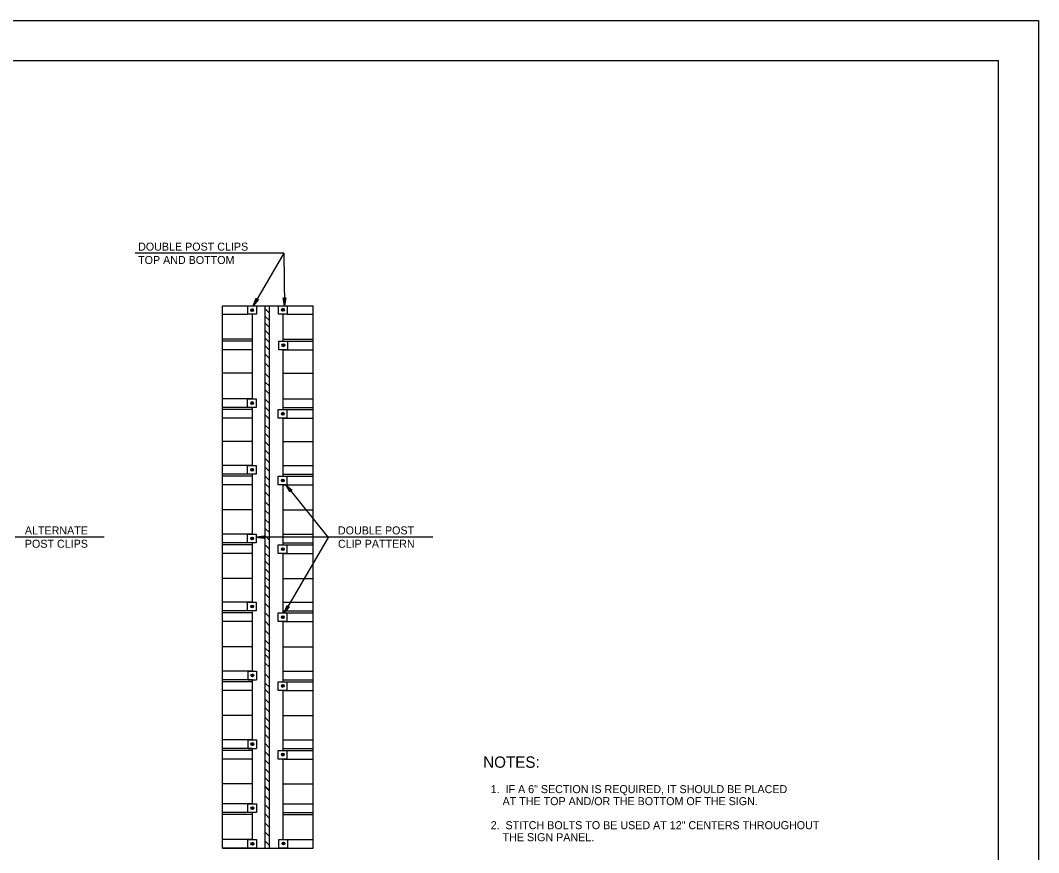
# Model space of a CAD drawing. Extents: x 647822 to 649292, y 298458 to 299646.
# Drawn here: x 648281.8 to 648663.3, y 299333.8 to 299645.6 of the extents above; entities that cross this region are included whole.
import ezdxf

# ---------------------------------------------------------------- set-up
doc = ezdxf.new("R2010")
doc.units = 0
for name, color, linetype in [('1', 7, 'Continuous'), ('2', 7, 'Continuous'), ('3', 7, 'Continuous'), ('XCS-GRID-MIN', 7, 'Continuous')]:
    doc.layers.add(name, color=color, linetype=linetype)

# ---------------------------------------------------------------- blocks, each defined once
blk = doc.blocks.new('RARROW')
at = {"layer": '3'}
blk.add_lwpolyline([(-2.2695, 0.285), (-2.184875, 0.12075), (0, 0), (-2.2695, 0.285), (-2.38575, 0.384625), (0, 0), (-2.183125, -0.108), (-2.262875, -0.2705), (0, 0), (-2.38575, -0.379125), (-2.262875, -0.2705)], dxfattribs=at)

msp = doc.modelspace()

# ---------------------------------------------------------------- linework, layer by layer
at = {"layer": '1'}
for p in [(647862.31, 299630.63), (648648.31, 299066.63)]:
    msp.add_line(p, (648648.31, 299630.63), dxfattribs=at)
at = {"layer": '2'}
for p, q in [((648380.55, 299558.35), (648324.89, 299558.35)), ((648380.55, 299558.35), (648369.05, 299538.73)), ((648380.55, 299558.35), (648380.8, 299538.73)), ((648357.55, 299335.47), (648357.55, 299538.73)), ((648357.55, 299538.73), (648391.55, 299538.73)), ((648367.05, 299535.6), (648367.05, 299538.73)), ((648370.3, 299538.73), (648370.3, 299535.6)), ((648373.55, 299335.47), (648373.55, 299538.73)), ((648375.18, 299535.98), (648373.55, 299537.6)), ((648375.18, 299335.47), (648375.18, 299538.73)), ((648378.55, 299538.73), (648381.8, 299538.73)), ((648378.55, 299535.6), (648378.55, 299538.73)), ((648381.8, 299538.73), (648381.8, 299535.6)), ((648391.55, 299335.47), (648391.55, 299538.73)), ((648357.55, 299535.6), (648367.05, 299535.6)), ((648370.3, 299535.6), (648367.05, 299535.6)), ((648368.8, 299503.85), (648368.8, 299535.6)), ((648375.18, 299533.23), (648373.55, 299534.73)), ((648381.8, 299535.6), (648378.55, 299535.6)), ((648380.3, 299525.48), (648380.3, 299535.6)), ((648381.8, 299535.6), (648391.55, 299535.6)), ((648375.18, 299530.6), (648373.55, 299532.23)), ((648368.8, 299526.23), (648357.55, 299526.23)), ((648375.18, 299527.85), (648373.55, 299529.48)), ((648375.18, 299524.98), (648373.55, 299526.6)), ((648380.3, 299526.23), (648391.55, 299526.23)), ((648368.8, 299525.48), (648357.55, 299525.48)), ((648368.8, 299522.23), (648357.55, 299522.23)), ((648375.18, 299522.1), (648373.55, 299523.73)), ((648378.68, 299525.48), (648381.93, 299525.48)), ((648378.68, 299522.23), (648378.68, 299525.48)), ((648381.93, 299522.23), (648378.68, 299522.23)), ((648380.3, 299525.48), (648391.55, 299525.48)), ((648380.3, 299525.48), (648380.3, 299525.48)), ((648380.3, 299522.23), (648391.55, 299522.23)), ((648380.3, 299499.85), (648380.3, 299522.23)), ((648381.93, 299525.48), (648381.93, 299522.23)), ((648375.18, 299518.98), (648373.55, 299520.6)), ((648375.18, 299515.6), (648373.55, 299517.23)), ((648368.8, 299513.48), (648357.55, 299513.48)), ((648375.18, 299511.73), (648373.55, 299513.35)), ((648380.3, 299513.48), (648391.55, 299513.48)), ((648375.18, 299508.6), (648373.55, 299510.1)), ((648375.18, 299505.6), (648373.55, 299507.23)), ((648368.8, 299503.85), (648357.55, 299503.85)), ((648366.93, 299503.85), (648370.18, 299503.85)), ((648366.93, 299500.6), (648366.93, 299503.85)), ((648370.18, 299503.85), (648370.18, 299500.6)), ((648375.18, 299502.1), (648373.55, 299503.73)), ((648380.3, 299503.85), (648391.55, 299503.85)), ((648368.8, 299500.6), (648357.55, 299500.6)), ((648368.8, 299499.85), (648357.55, 299499.85)), ((648370.18, 299500.6), (648366.93, 299500.6)), ((648368.8, 299478.85), (648368.8, 299500.6)), ((648375.18, 299499.1), (648373.55, 299500.73)), ((648378.43, 299499.85), (648381.68, 299499.85)), ((648378.43, 299496.6), (648378.43, 299499.85)), ((648380.3, 299500.6), (648391.55, 299500.6)), ((648380.3, 299499.85), (648391.55, 299499.85)), ((648381.68, 299499.85), (648381.68, 299496.6)), ((648368.8, 299496.6), (648357.55, 299496.6)), ((648375.18, 299496.23), (648373.55, 299497.85)), ((648381.68, 299496.6), (648378.43, 299496.6)), ((648380.3, 299496.6), (648391.55, 299496.6)), ((648380.3, 299474.85), (648380.3, 299496.6)), ((648375.18, 299492.48), (648373.55, 299493.98)), ((648368.8, 299487.85), (648357.55, 299487.85)), ((648375.18, 299489.23), (648373.55, 299490.85)), ((648380.3, 299487.85), (648391.55, 299487.85)), ((648375.18, 299486.1), (648373.55, 299487.73)), ((648375.18, 299482.98), (648373.55, 299484.6)), ((648375.18, 299479.85), (648373.55, 299481.48)), ((648368.8, 299478.85), (648357.55, 299478.85)), ((648366.93, 299478.85), (648370.18, 299478.85)), ((648366.93, 299475.6), (648366.93, 299478.85)), ((648370.18, 299478.85), (648370.18, 299475.6)), ((648375.18, 299476.6), (648373.55, 299478.23)), ((648380.3, 299478.85), (648391.55, 299478.85)), ((648368.8, 299475.6), (648357.55, 299475.6)), ((648368.8, 299474.85), (648357.55, 299474.85)), ((648370.18, 299475.6), (648366.93, 299475.6)), ((648368.8, 299453.47), (648368.8, 299475.6)), ((648375.18, 299473.23), (648373.55, 299474.85)), ((648378.43, 299474.85), (648381.68, 299474.85)), ((648378.43, 299471.6), (648378.43, 299474.85)), ((648380.3, 299475.6), (648391.55, 299475.6)), ((648380.3, 299474.85), (648391.55, 299474.85)), ((648381.68, 299474.85), (648381.68, 299471.6)), ((648368.8, 299471.6), (648357.55, 299471.6)), ((648375.18, 299470.48), (648373.55, 299471.98)), ((648375.18, 299467.23), (648373.55, 299468.85)), ((648381.68, 299471.6), (648378.43, 299471.6)), ((648380.3, 299471.6), (648391.55, 299471.6)), ((648380.3, 299449.36), (648380.3, 299471.6)), ((648381.32, 299471.6), (648397.18, 299451.85)), ((648375.18, 299463.6), (648373.55, 299465.23)), ((648368.8, 299462.23), (648357.55, 299462.23)), ((648375.18, 299460.48), (648373.55, 299461.98)), ((648380.3, 299462.23), (648391.55, 299462.23)), ((648375.18, 299457.1), (648373.55, 299458.6)), ((648375.18, 299453.73), (648373.55, 299455.23)), ((648313.17, 299451.98), (648279.88, 299451.98)), ((648368.8, 299453.1), (648357.55, 299453.1)), ((648368.8, 299449.85), (648357.55, 299449.85)), ((648366.93, 299453.1), (648370.18, 299453.1)), ((648366.93, 299449.85), (648366.93, 299453.1)), ((648370.18, 299449.85), (648366.93, 299449.85)), ((648368.55, 299453.1), (648368.55, 299453.1)), ((648368.8, 299427.6), (648368.8, 299449.85)), ((648370.18, 299453.1), (648370.18, 299449.85)), ((648397.43, 299451.98), (648370.3, 299451.98)), ((648375.18, 299450.85), (648373.55, 299452.48)), ((648380.3, 299453.1), (648391.55, 299453.1)), ((648380.3, 299449.85), (648391.55, 299449.85)), ((648397.18, 299451.85), (648380.71, 299423.6)), ((648436.31, 299451.98), (648397.18, 299451.98)), ((648368.8, 299449.1), (648357.55, 299449.1)), ((648368.8, 299445.85), (648357.55, 299445.85)), ((648375.18, 299447.48), (648373.55, 299449.1)), ((648375.18, 299444.48), (648373.55, 299445.98)), ((648378.43, 299449.1), (648381.68, 299449.1)), ((648378.43, 299445.85), (648378.43, 299449.1)), ((648381.68, 299445.85), (648378.43, 299445.85)), ((648380.05, 299449.1), (648380.05, 299449.1)), ((648380.3, 299449.1), (648391.55, 299449.1)), ((648380.3, 299445.85), (648391.55, 299445.85)), ((648380.3, 299423.6), (648380.3, 299445.85)), ((648381.68, 299449.1), (648381.68, 299445.85)), ((648375.18, 299441.35), (648373.55, 299442.98)), ((648375.18, 299438.48), (648373.55, 299440.1)), ((648368.8, 299436.48), (648357.55, 299436.48)), ((648375.18, 299435.48), (648373.55, 299436.98)), ((648380.3, 299436.48), (648391.55, 299436.48)), ((648375.05, 299432.48), (648373.55, 299433.98)), ((648375.18, 299432.48), (648373.55, 299433.98)), ((648375.18, 299429.1), (648373.55, 299430.73)), ((648368.68, 299427.6), (648357.43, 299427.6)), ((648366.93, 299427.6), (648370.18, 299427.6)), ((648366.93, 299424.35), (648366.93, 299427.6)), ((648368.55, 299427.6), (648368.55, 299427.6)), ((648370.18, 299427.6), (648370.18, 299424.35)), ((648375.18, 299425.48), (648373.55, 299427.1)), ((648380.3, 299427.6), (648391.55, 299427.6)), ((648368.68, 299424.35), (648357.43, 299424.35)), ((648368.68, 299423.6), (648357.43, 299423.6)), ((648370.18, 299424.35), (648366.93, 299424.35)), ((648368.8, 299401.85), (648368.8, 299424.02)), ((648375.18, 299421.98), (648373.55, 299423.6)), ((648378.43, 299423.6), (648381.68, 299423.6)), ((648378.43, 299420.35), (648378.43, 299423.6)), ((648380.05, 299423.6), (648380.05, 299423.6)), ((648380.3, 299424.35), (648391.55, 299424.35)), ((648380.3, 299423.6), (648391.55, 299423.6)), ((648381.68, 299423.6), (648381.68, 299420.35)), ((648368.68, 299420.35), (648357.43, 299420.35)), ((648375.18, 299418.73), (648373.68, 299420.35)), ((648381.68, 299420.35), (648378.43, 299420.35)), ((648380.3, 299420.35), (648391.55, 299420.35)), ((648380.3, 299397.85), (648380.3, 299420.27)), ((648375.18, 299415.35), (648373.55, 299416.98)), ((648375.18, 299411.73), (648373.55, 299413.35)), ((648368.8, 299410.85), (648357.55, 299410.85)), ((648375.18, 299408.85), (648373.55, 299410.35)), ((648375.18, 299406.35), (648373.55, 299407.98)), ((648380.3, 299410.85), (648391.55, 299410.85)), ((648375.18, 299403.23), (648373.55, 299404.85)), ((648368.8, 299401.85), (648357.55, 299401.85)), ((648367.18, 299401.85), (648370.3, 299401.85)), ((648367.18, 299398.6), (648367.18, 299401.85)), ((648368.8, 299401.85), (648368.8, 299401.85)), ((648370.3, 299401.85), (648370.3, 299398.6)), ((648375.18, 299399.1), (648373.55, 299400.73)), ((648380.3, 299401.85), (648391.55, 299401.85)), ((648368.8, 299398.6), (648357.55, 299398.6)), ((648368.8, 299397.85), (648357.55, 299397.85)), ((648368.8, 299398.6), (648367.18, 299398.6)), ((648367.18, 299398.6), (648370.3, 299398.6)), ((648368.8, 299376.1), (648368.8, 299398.6)), ((648375.18, 299395.85), (648373.55, 299397.35)), ((648378.43, 299397.85), (648381.68, 299397.85)), ((648378.43, 299394.6), (648378.43, 299397.85)), ((648380.05, 299397.85), (648380.05, 299397.85)), ((648380.3, 299398.6), (648391.55, 299398.6)), ((648380.3, 299397.85), (648391.55, 299397.85)), ((648381.68, 299397.85), (648381.68, 299394.6)), ((648368.8, 299394.6), (648357.55, 299394.6)), ((648375.18, 299393.35), (648373.55, 299394.98)), ((648381.68, 299394.6), (648378.43, 299394.6)), ((648380.3, 299394.6), (648391.55, 299394.6)), ((648380.3, 299372.1), (648380.3, 299394.6)), ((648375.18, 299389.73), (648373.55, 299391.35)), ((648368.8, 299385.23), (648357.55, 299385.23)), ((648375.18, 299386.48), (648373.55, 299388.1)), ((648380.3, 299385.23), (648391.55, 299385.23)), ((648375.18, 299382.85), (648373.55, 299384.48)), ((648375.18, 299379.85), (648373.55, 299381.48)), ((648375.18, 299376.48), (648373.55, 299378.1)), ((648368.8, 299376.1), (648357.55, 299376.1)), ((648367.18, 299376.1), (648370.3, 299376.1)), ((648367.18, 299372.85), (648367.18, 299376.1)), ((648368.8, 299376.1), (648368.8, 299376.1)), ((648370.3, 299376.1), (648370.3, 299372.85)), ((648375.05, 299373.1), (648373.55, 299374.73)), ((648380.3, 299376.1), (648391.55, 299376.1)), ((648368.8, 299372.85), (648357.55, 299372.85)), ((648368.8, 299372.1), (648357.55, 299372.1)), ((648368.8, 299372.85), (648367.18, 299372.85)), ((648367.18, 299372.85), (648370.3, 299372.85)), ((648368.8, 299352.1), (648368.8, 299372.85)), ((648375.05, 299370.1), (648373.55, 299371.6)), ((648378.43, 299372.1), (648381.68, 299372.1)), ((648378.43, 299368.85), (648378.43, 299372.1)), ((648380.3, 299372.85), (648391.55, 299372.85)), ((648380.3, 299372.1), (648391.55, 299372.1)), ((648381.68, 299372.1), (648381.68, 299368.85)), ((648368.8, 299368.85), (648357.55, 299368.85)), ((648375.18, 299366.85), (648373.55, 299368.48)), ((648381.68, 299368.85), (648378.43, 299368.85)), ((648380.3, 299368.85), (648391.55, 299368.85)), ((648380.3, 299348.05), (648380.3, 299368.85)), ((648375.18, 299363.6), (648373.68, 299365.1)), ((648368.8, 299359.6), (648357.55, 299359.6)), ((648375.18, 299360.23), (648373.55, 299361.85)), ((648375.18, 299360.23), (648373.55, 299361.85)), ((648375.05, 299357.23), (648373.55, 299358.73)), ((648375.18, 299356.83), (648373.55, 299358.46)), ((648380.3, 299359.6), (648391.55, 299359.6)), ((648375.18, 299353.44), (648373.55, 299355.06)), ((648368.68, 299352.1), (648357.55, 299352.1)), ((648367.05, 299352.1), (648370.3, 299352.1)), ((648367.05, 299348.85), (648367.05, 299352.1)), ((648370.3, 299352.1), (648370.3, 299348.85)), ((648375.18, 299350.04), (648373.55, 299351.67)), ((648380.43, 299352.1), (648391.55, 299352.1)), ((648368.68, 299348.85), (648357.55, 299348.85)), ((648368.8, 299348.05), (648357.55, 299348.05)), ((648370.3, 299348.85), (648367.05, 299348.85)), ((648368.8, 299338.72), (648368.8, 299348.85)), ((648375.18, 299346.65), (648373.55, 299348.28)), ((648380.3, 299348.85), (648391.55, 299348.85)), ((648380.3, 299338.72), (648380.3, 299348.05)), ((648380.3, 299348.05), (648391.55, 299348.05)), ((648375.18, 299343.26), (648373.55, 299344.88)), ((648375.18, 299339.86), (648373.55, 299341.49)), ((648368.68, 299338.72), (648357.55, 299338.72)), ((648357.55, 299335.47), (648391.55, 299335.47)), ((648368.68, 299335.47), (648357.55, 299335.47)), ((648367.05, 299338.72), (648370.3, 299338.72)), ((648367.05, 299335.47), (648367.05, 299338.72)), ((648370.3, 299335.47), (648367.05, 299335.47)), ((648370.3, 299338.72), (648370.3, 299335.47)), ((648375.18, 299336.47), (648373.55, 299338.09)), ((648378.68, 299338.72), (648381.93, 299338.72)), ((648378.68, 299335.47), (648378.68, 299338.72)), ((648381.93, 299335.47), (648378.68, 299335.47)), ((648380.43, 299338.72), (648391.55, 299338.72)), ((648380.43, 299335.47), (648391.55, 299335.47)), ((648381.93, 299338.72), (648381.93, 299335.47))]:
    msp.add_line(p, q, dxfattribs=at)
for points in [[(648368.55, 299537.48), (648368.43, 299537.23), (648368.43, 299536.85), (648368.68, 299536.73), (648368.93, 299536.85), (648369.05, 299537.1), (648369.05, 299537.35), (648368.93, 299537.48), (648368.68, 299537.48), (648368.55, 299537.23), (648368.55, 299537.1), (648368.55, 299536.98), (648368.68, 299536.98), (648368.8, 299537.1), (648368.93, 299537.23), (648368.8, 299537.35), (648368.8, 299537.23), (648368.68, 299537.1)], [(648380.05, 299537.6), (648379.93, 299537.23), (648379.93, 299536.98), (648380.18, 299536.85), (648380.43, 299536.98), (648380.55, 299537.23), (648380.55, 299537.48), (648380.43, 299537.6), (648380.18, 299537.48), (648380.05, 299537.23), (648380.05, 299537.1), (648380.05, 299537.1), (648380.18, 299536.98), (648380.3, 299537.23), (648380.43, 299537.23), (648380.3, 299537.48), (648380.3, 299537.35), (648380.18, 299537.1)], [(648380.18, 299524.35), (648380.05, 299523.98), (648380.05, 299523.73), (648380.3, 299523.48), (648380.55, 299523.6), (648380.68, 299523.85), (648380.68, 299524.1), (648380.55, 299524.35), (648380.43, 299524.23), (648380.18, 299523.98), (648380.18, 299523.85), (648380.18, 299523.73), (648380.3, 299523.73), (648380.43, 299523.85), (648380.55, 299523.98), (648380.55, 299524.1), (648380.43, 299523.98), (648380.3, 299523.85)], [(648368.55, 299502.6), (648368.3, 299502.35), (648368.3, 299501.98), (648368.55, 299501.85), (648368.8, 299501.98), (648368.93, 299502.23), (648368.93, 299502.48), (648368.8, 299502.6), (648368.68, 299502.6), (648368.43, 299502.35), (648368.43, 299502.23), (648368.43, 299502.1), (648368.68, 299502.1), (648368.8, 299502.23), (648368.8, 299502.35), (648368.8, 299502.48), (648368.68, 299502.35), (648368.55, 299502.23)], [(648380.05, 299498.6), (648379.8, 299498.35), (648379.8, 299497.98), (648380.05, 299497.85), (648380.3, 299497.98), (648380.43, 299498.23), (648380.43, 299498.48), (648380.3, 299498.6), (648380.18, 299498.6), (648379.93, 299498.35), (648379.93, 299498.23), (648379.93, 299498.1), (648380.18, 299498.1), (648380.3, 299498.23), (648380.3, 299498.35), (648380.3, 299498.48), (648380.18, 299498.35), (648380.05, 299498.23)], [(648368.55, 299477.6), (648368.3, 299477.35), (648368.3, 299476.98), (648368.55, 299476.85), (648368.8, 299476.98), (648368.93, 299477.23), (648368.93, 299477.48), (648368.8, 299477.6), (648368.68, 299477.6), (648368.43, 299477.35), (648368.43, 299477.23), (648368.43, 299477.1), (648368.68, 299477.1), (648368.8, 299477.23), (648368.8, 299477.35), (648368.8, 299477.48), (648368.68, 299477.35), (648368.55, 299477.23)], [(648380.05, 299473.6), (648379.8, 299473.35), (648379.8, 299472.98), (648380.05, 299472.85), (648380.3, 299472.98), (648380.43, 299473.23), (648380.43, 299473.48), (648380.3, 299473.6), (648380.18, 299473.6), (648379.93, 299473.35), (648379.93, 299473.23), (648379.93, 299473.1), (648380.18, 299473.1), (648380.3, 299473.23), (648380.3, 299473.35), (648380.3, 299473.48), (648380.18, 299473.35), (648380.05, 299473.23)], [(648368.55, 299451.85), (648368.3, 299451.6), (648368.3, 299451.23), (648368.55, 299451.1), (648368.8, 299451.23), (648368.93, 299451.48), (648368.93, 299451.73), (648368.8, 299451.85), (648368.68, 299451.85), (648368.43, 299451.6), (648368.43, 299451.48), (648368.43, 299451.35), (648368.68, 299451.35), (648368.8, 299451.48), (648368.8, 299451.6), (648368.8, 299451.73), (648368.68, 299451.6), (648368.55, 299451.48)], [(648380.05, 299447.85), (648379.8, 299447.6), (648379.8, 299447.23), (648380.05, 299447.1), (648380.3, 299447.23), (648380.43, 299447.48), (648380.43, 299447.73), (648380.3, 299447.85), (648380.18, 299447.85), (648379.93, 299447.6), (648379.93, 299447.48), (648379.93, 299447.35), (648380.18, 299447.35), (648380.3, 299447.48), (648380.3, 299447.6), (648380.3, 299447.73), (648380.18, 299447.6), (648380.05, 299447.48)], [(648368.55, 299426.35), (648368.3, 299426.1), (648368.3, 299425.73), (648368.55, 299425.6), (648368.8, 299425.73), (648368.93, 299425.98), (648368.93, 299426.23), (648368.8, 299426.35), (648368.68, 299426.35), (648368.43, 299426.1), (648368.43, 299425.98), (648368.43, 299425.85), (648368.68, 299425.85), (648368.8, 299425.98), (648368.8, 299426.1), (648368.8, 299426.23), (648368.68, 299426.1), (648368.55, 299425.98)], [(648380.05, 299422.35), (648379.8, 299422.1), (648379.8, 299421.73), (648380.05, 299421.6), (648380.3, 299421.73), (648380.43, 299421.98), (648380.43, 299422.23), (648380.3, 299422.35), (648380.18, 299422.35), (648379.93, 299422.1), (648379.93, 299421.98), (648379.93, 299421.85), (648380.18, 299421.85), (648380.3, 299421.98), (648380.3, 299422.1), (648380.3, 299422.23), (648380.18, 299422.1), (648380.05, 299421.98)], [(648368.55, 299400.6), (648368.43, 299400.23), (648368.43, 299399.98), (648368.68, 299399.85), (648368.93, 299399.98), (648369.05, 299400.23), (648369.05, 299400.48), (648368.93, 299400.6), (648368.8, 299400.48), (648368.55, 299400.23), (648368.55, 299400.1), (648368.55, 299400.1), (648368.68, 299399.98), (648368.8, 299400.23), (648368.93, 299400.23), (648368.93, 299400.48), (648368.8, 299400.35), (648368.68, 299400.1)], [(648380.05, 299396.6), (648379.8, 299396.35), (648379.8, 299395.98), (648380.05, 299395.85), (648380.3, 299395.98), (648380.43, 299396.23), (648380.43, 299396.48), (648380.3, 299396.6), (648380.18, 299396.6), (648379.93, 299396.35), (648379.93, 299396.23), (648379.93, 299396.1), (648380.18, 299396.1), (648380.3, 299396.23), (648380.3, 299396.35), (648380.3, 299396.48), (648380.18, 299396.35), (648380.05, 299396.23)], [(648368.55, 299374.85), (648368.43, 299374.48), (648368.43, 299374.23), (648368.68, 299374.1), (648368.93, 299374.23), (648369.05, 299374.48), (648369.05, 299374.73), (648368.93, 299374.85), (648368.8, 299374.73), (648368.55, 299374.48), (648368.55, 299374.35), (648368.55, 299374.35), (648368.68, 299374.23), (648368.8, 299374.48), (648368.93, 299374.48), (648368.93, 299374.73), (648368.8, 299374.6), (648368.68, 299374.35)], [(648380.05, 299370.85), (648379.8, 299370.6), (648379.8, 299370.23), (648380.05, 299370.1), (648380.3, 299370.23), (648380.43, 299370.48), (648380.43, 299370.73), (648380.3, 299370.85), (648380.18, 299370.85), (648379.93, 299370.6), (648379.93, 299370.48), (648379.93, 299370.35), (648380.18, 299370.35), (648380.3, 299370.48), (648380.3, 299370.6), (648380.3, 299370.73), (648380.18, 299370.6), (648380.05, 299370.48)], [(648368.55, 299350.85), (648368.43, 299350.48), (648368.43, 299350.23), (648368.68, 299350.1), (648368.93, 299350.23), (648369.05, 299350.35), (648369.05, 299350.73), (648368.93, 299350.85), (648368.68, 299350.85), (648368.55, 299350.48), (648368.55, 299350.35), (648368.55, 299350.23), (648368.68, 299350.23), (648368.8, 299350.35), (648368.93, 299350.48), (648368.93, 299350.73), (648368.8, 299350.6), (648368.68, 299350.35)], [(648368.55, 299337.47), (648368.43, 299337.09), (648368.43, 299336.84), (648368.68, 299336.72), (648368.93, 299336.84), (648369.05, 299336.97), (648369.05, 299337.34), (648368.93, 299337.47), (648368.68, 299337.47), (648368.55, 299337.09), (648368.55, 299336.97), (648368.55, 299336.84), (648368.68, 299336.84), (648368.8, 299336.97), (648368.93, 299337.09), (648368.93, 299337.34), (648368.8, 299337.22), (648368.68, 299336.97)], [(648380.3, 299337.59), (648380.05, 299337.22), (648380.05, 299336.97), (648380.43, 299336.84), (648380.68, 299336.97), (648380.8, 299337.22), (648380.8, 299337.47), (648380.55, 299337.59), (648380.43, 299337.59), (648380.3, 299337.22), (648380.18, 299337.22), (648380.3, 299336.97), (648380.43, 299336.97), (648380.55, 299337.22), (648380.68, 299337.22), (648380.55, 299337.47), (648380.43, 299337.34), (648380.43, 299337.22)]]:
    msp.add_lwpolyline(points, dxfattribs=at)
for centre in [(648368.68, 299537.06), (648380.21, 299537.23), (648380.36, 299523.97), (648368.64, 299502.26), (648380.14, 299498.26), (648368.64, 299477.26), (648380.14, 299473.26), (648368.64, 299451.51), (648380.14, 299447.51), (648368.64, 299426.01), (648380.14, 299422.01), (648368.74, 299400.23), (648380.14, 299396.26), (648368.74, 299374.48), (648380.14, 299370.51), (648368.73, 299350.48), (648368.73, 299337.1), (648380.43, 299337.22)]:
    msp.add_circle(centre, 0.525, dxfattribs=at)
at = {"layer": 'XCS-GRID-MIN'}
msp.add_lwpolyline([(647822.31, 299645.63), (648663.31, 299645.63), (648663.31, 299051.63), (647822.31, 299051.63)], close=True, dxfattribs=at)

# ---------------------------------------------------------------- block references
at = {"layer": '2'}
for p, xscale, yscale, rotation in [((648369.05, 299538.73), 1.2574347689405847, 1.3092961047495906, -120.49730409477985), ((648380.8, 299538.73), 1.2574347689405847, 1.3092961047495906, -90.00000000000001), ((648381.32, 299471.6), 1.2574347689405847, 1.3092961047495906, 128.86004763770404), ((648370.3, 299451.98), 1.2574347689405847, 1.3092961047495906, 180), ((648380.71, 299423.6), 1.2574347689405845, 1.3092961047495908, -120.047510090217)]:
    msp.add_blockref('RARROW', p, dxfattribs=dict(at, xscale=xscale, yscale=yscale, rotation=rotation))

# ---------------------------------------------------------------- texts
for s, height, p in [('DOUBLE POST CLIPS', 3, (648325.93, 299559.35)), ('TOP AND BOTTOM', 3, (648325.93, 299554.35)), ('ALTERNATE', 3, (648283.5, 299453.03)), ('DOUBLE POST', 3, (648400.8, 299453.03)), ('POST CLIPS', 3, (648283.5, 299448.03)), ('CLIP PATTERN', 3, (648400.8, 299448.03)), ('NOTES:', 4.25, (648455.22, 299365.59)), ('1.  IF A 6" SECTION IS REQUIRED, IT SHOULD BE PLACED', 3, (648458.02, 299356.09)), ('    AT THE TOP AND/OR THE BOTTOM OF THE SIGN.', 3, (648458.02, 299351.59)), ('2.  STITCH BOLTS TO BE USED AT 12" CENTERS THROUGHOUT', 3, (648458.02, 299342.59)), ('    THE SIGN PANEL.', 3, (648458.02, 299338.09))]:
    msp.add_text(s, height=height, dxfattribs=at).set_placement(p)

doc.saveas('drawing.dxf')
